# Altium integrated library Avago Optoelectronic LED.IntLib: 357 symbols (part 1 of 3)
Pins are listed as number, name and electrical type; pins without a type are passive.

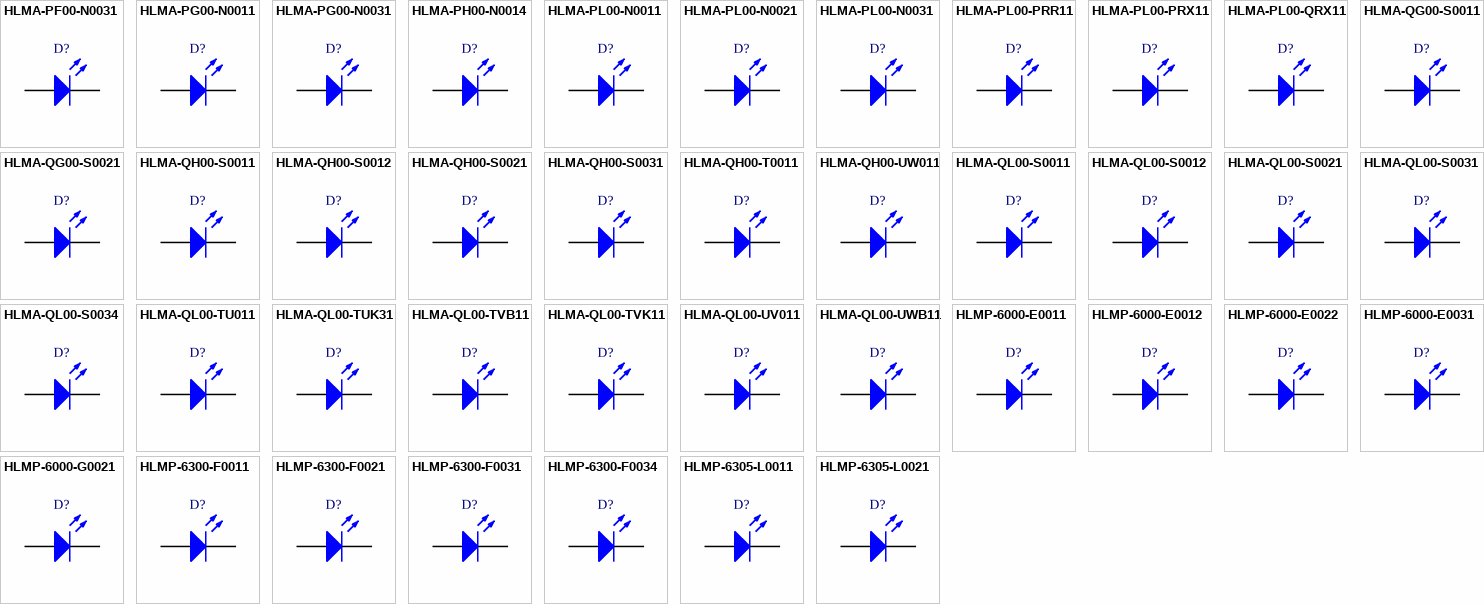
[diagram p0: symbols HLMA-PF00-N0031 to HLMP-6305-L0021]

## HLMA-PF00-N0031
designator D?
Subminiature High Performance AlInGaP Red LED Lamp; LuminousIntensity: 25mcd (Minimum).; PCB_Layout: Complies with manufacturer's recommendation.; DrillSize: Nominal, Rounded to nearest 0.05mm
footprint 2.2X2.1X2.2Z (SM LED; 2 Z-Bend Leads)
simulation model Agl_HLMPQG00 (Diode)
signal-integrity model LED
pins: 1 A, 2 K

## HLMA-PG00-N0011
designator D?
Subminiature High Performance AlInGaP Red LED Lamp; LuminousIntensity: 25mcd (Minimum).; PCB_Layout: Complies with manufacturer's recommendation.
footprint 2.2X2.1X2.2 (SM LED; 2 Gull Wing Leads; Body 2.2 x 2.1 mm, (LxW))
simulation model Agl_HLMPQG00 (Diode)
signal-integrity model LED
pins: 1 A, 2 K

## HLMA-PG00-N0031
designator D?
Subminiature High Performance AlInGaP Red LED Lamp; LuminousIntensity: 25mcd (Minimum).; PCB_Layout: Complies with manufacturer's recommendation.; DrillSize: Nominal, Rounded to nearest 0.05mm
footprint 2.2X2.1X2.2Z (SM LED; 2 Z-Bend Leads)
simulation model Agl_HLMPQG00 (Diode)
signal-integrity model LED
pins: 1 A, 2 K

## HLMA-PH00-N0014
designator D?
Subminiature High Performance AlInGaP Red/Orange LED Lamp; LuminousIntensity: 25mcd (Minimum).; LED_Colour: Red & Orange; PCB_Layout: Complies with manufacturer's recommendation.
footprint 2.2X2.1X2.2 (SM LED; 2 Gull Wing Leads; Body 2.2 x 2.1 mm, (LxW))
simulation model Agl_HLMPQG00 (Diode)
signal-integrity model LED
pins: 1 A, 2 K

## HLMA-PL00-N0011
designator D?
Subminiature High Performance AlInGaP Amber LED Lamp; LuminousIntensity: 25mcd (Minimum).; PCB_Layout: Complies with manufacturer's recommendation.
footprint 2.2X2.1X2.2 (SM LED; 2 Gull Wing Leads; Body 2.2 x 2.1 mm, (LxW))
simulation model Agl_HLMPQG00 (Diode)
signal-integrity model LED
pins: 1 A, 2 K

## HLMA-PL00-N0021
designator D?
Subminiature High Performance AlInGaP Amber LED Lamp; LuminousIntensity: 25mcd (Minimum).; PCB_Layout: Complies with manufacturer's recommendation.; DrillSize: Nominal, Rounded to nearest 0.05mm
footprint 2.2X2.1X2.2Y (SM LED; 2 Yoke Leads)
simulation model Agl_HLMPQG00 (Diode)
signal-integrity model LED
pins: 1 A, 2 K

## HLMA-PL00-N0031
designator D?
Subminiature High Performance AlInGaP Amber LED Lamp; LuminousIntensity: 25mcd (Minimum).; PCB_Layout: Complies with manufacturer's recommendation.; DrillSize: Nominal, Rounded to nearest 0.05mm
footprint 2.2X2.1X2.2Z (SM LED; 2 Z-Bend Leads)
simulation model Agl_HLMPQG00 (Diode)
signal-integrity model LED
pins: 1 A, 2 K

## HLMA-PL00-PRR11
designator D?
Subminiature High Performance AlInGaP Amber LED Lamp; LuminousIntensity: 40mcd (Minimum).; PCB_Layout: Complies with manufacturer's recommendation.
footprint 2.2X2.1X2.2 (SM LED; 2 Gull Wing Leads; Body 2.2 x 2.1 mm, (LxW))
simulation model Agl_HLMPQG00 (Diode)
signal-integrity model LED
pins: 1 A, 2 K

## HLMA-PL00-PRX11
designator D?
Subminiature High Performance AlInGaP Amber LED Lamp; LuminousIntensity: 40mcd (Minimum).; PCB_Layout: Complies with manufacturer's recommendation.
footprint 2.2X2.1X2.2 (SM LED; 2 Gull Wing Leads; Body 2.2 x 2.1 mm, (LxW))
simulation model Agl_HLMPQG00 (Diode)
signal-integrity model LED
pins: 1 A, 2 K

## HLMA-PL00-QRX11
designator D?
Subminiature High Performance AlInGaP Amber LED Lamp; LuminousIntensity: 63mcd (Minimum).; PCB_Layout: Complies with manufacturer's recommendation.
footprint 2.2X2.1X2.2 (SM LED; 2 Gull Wing Leads; Body 2.2 x 2.1 mm, (LxW))
simulation model Agl_HLMPQG00 (Diode)
signal-integrity model LED
pins: 1 A, 2 K

## HLMA-QG00-S0011
designator D?
Subminiature High Performance AS AlInGaP Red LED Lamp; LuminousIntensity: 160mcd (Minimum).; PCB_Layout: Complies with manufacturer's recommendation.; DrillSize: Nominal, Rounded to nearest 0.05mm
footprint 2.2X2.1X2.9 (SM LED; 2 Gull Wing Leads; Body 2.2 x 2.1 mm, (LxW))
simulation model Agl_HLMPQG00 (Diode)
signal-integrity model LED
pins: 1 A, 2 K

## HLMA-QG00-S0021
designator D?
Subminiature High Performance AS AlInGaP Red LED Lamp; LuminousIntensity: 160mcd (Minimum).; PCB_Layout: Complies with manufacturer's recommendation.; DrillSize: Nominal, Rounded to nearest 0.05mm
footprint 2.2X2.1X2.9Y (SM LED; 2 Yoke Leads)
simulation model Agl_HLMPQG00 (Diode)
signal-integrity model LED
pins: 1 A, 2 K

## HLMA-QH00-S0011
designator D?
Subminiature High Performance AS AlInGaP Red/Orange LED Lamp; LuminousIntensity: 160mcd (Minimum).; LED_Colour: Red & Orange; PCB_Layout: Complies with manufacturer's recommendation.
footprint 2.2X2.1X2.9 (SM LED; 2 Gull Wing Leads; Body 2.2 x 2.1 mm, (LxW))
simulation model Agl_HLMPQG00 (Diode)
signal-integrity model LED
pins: 1 A, 2 K

## HLMA-QH00-S0012
designator D?
Subminiature High Performance AS AlInGaP Red/Orange LED Lamp; LuminousIntensity: 160mcd (Minimum).; LED_Colour: Red & Orange; PCB_Layout: Complies with manufacturer's recommendation.
footprint 2.2X2.1X2.9 (SM LED; 2 Gull Wing Leads; Body 2.2 x 2.1 mm, (LxW))
simulation model Agl_HLMPQG00 (Diode)
signal-integrity model LED
pins: 1 A, 2 K

## HLMA-QH00-S0021
designator D?
Subminiature High Performance AlInGaP Red/Orange LED Lamp; LuminousIntensity: 160mcd (Minimum).; LED_Colour: Red & Orange; PCB_Layout: Complies with manufacturer's recommendation.; DrillSize: Nominal, Rounded to nearest 0.05mm
footprint 2.2X2.1X2.9Y (SM LED; 2 Yoke Leads)
simulation model Agl_HLMPQG00 (Diode)
signal-integrity model LED
pins: 1 A, 2 K

## HLMA-QH00-S0031
designator D?
Subminiature High Performance AlInGaP Red/Orange LED Lamp; LuminousIntensity: 160mcd (Minimum).; LED_Colour: Red & Orange; PCB_Layout: Complies with manufacturer's recommendation.; DrillSize: Nominal, Rounded to nearest 0.05mm
footprint 2.2X2.1X2.9Z (SM LED; 2 Z-Bend Leads)
simulation model Agl_HLMPQG00 (Diode)
signal-integrity model LED
pins: 1 A, 2 K

## HLMA-QH00-T0011
designator D?
Subminiature High Performance AlInGaP Red/Orange LED Lamp; LuminousIntensity: 250mcd (Minimum).; LED_Colour: Red & Orange; PCB_Layout: Complies with manufacturer's recommendation.
footprint 2.2X2.1X2.9 (SM LED; 2 Gull Wing Leads; Body 2.2 x 2.1 mm, (LxW))
simulation model Agl_HLMPQG00 (Diode)
signal-integrity model LED
pins: 1 A, 2 K

## HLMA-QH00-UW011
designator D?
Subminiature High Performance AlInGaP Red/Orange LED Lamp; LuminousIntensity: 400mcd (Minimum).; LED_Colour: Red & Orange; PCB_Layout: Complies with manufacturer's recommendation.
footprint 2.2X2.1X2.9 (SM LED; 2 Gull Wing Leads; Body 2.2 x 2.1 mm, (LxW))
simulation model Agl_HLMPQG00 (Diode)
signal-integrity model LED
pins: 1 A, 2 K

## HLMA-QL00-S0011
designator D?
Subminiature High Performance AlInGaP Amber LED Lamp; LuminousIntensity: 160mcd (Minimum).; PCB_Layout: Complies with manufacturer's recommendation.
footprint 2.2X2.1X2.9 (SM LED; 2 Gull Wing Leads; Body 2.2 x 2.1 mm, (LxW))
simulation model Agl_HLMPQG00 (Diode)
signal-integrity model LED
pins: 1 A, 2 K

## HLMA-QL00-S0012
designator D?
Subminiature High Performance AlInGaP Amber LED Lamp; LuminousIntensity: 160mcd (Minimum).; PCB_Layout: Complies with manufacturer's recommendation.
footprint 2.2X2.1X2.9 (SM LED; 2 Gull Wing Leads; Body 2.2 x 2.1 mm, (LxW))
simulation model Agl_HLMPQG00 (Diode)
signal-integrity model LED
pins: 1 A, 2 K

## HLMA-QL00-S0021
designator D?
Subminiature High Performance AlInGaP Amber LED Lamp; LuminousIntensity: 160mcd (Minimum).; PCB_Layout: Complies with manufacturer's recommendation.; DrillSize: Nominal, Rounded to nearest 0.05mm
footprint 2.2X2.1X2.9Y (SM LED; 2 Yoke Leads)
simulation model Agl_HLMPQG00 (Diode)
signal-integrity model LED
pins: 1 A, 2 K

## HLMA-QL00-S0031
designator D?
Subminiature High Performance AlInGaP Amber LED Lamp; LuminousIntensity: 160mcd (Minimum).; PCB_Layout: Complies with manufacturer's recommendation.; DrillSize: Nominal, Rounded to nearest 0.05mm
footprint 2.2X2.1X2.9Z (SM LED; 2 Z-Bend Leads)
simulation model Agl_HLMPQG00 (Diode)
signal-integrity model LED
pins: 1 A, 2 K

## HLMA-QL00-S0034
designator D?
Subminiature High Performance AlInGaP Amber LED Lamp; LuminousIntensity: 160mcd (Minimum).; PCB_Layout: Complies with manufacturer's recommendation.; DrillSize: Nominal, Rounded to nearest 0.05mm
footprint 2.2X2.1X2.9Z (SM LED; 2 Z-Bend Leads)
simulation model Agl_HLMPQG00 (Diode)
signal-integrity model LED
pins: 1 A, 2 K

## HLMA-QL00-TU011
designator D?
Subminiature High Performance AlInGaP Amber LED Lamp; LuminousIntensity: 250mcd (Minimum).; PCB_Layout: Complies with manufacturer's recommendation.
footprint 2.2X2.1X2.9 (SM LED; 2 Gull Wing Leads; Body 2.2 x 2.1 mm, (LxW))
simulation model Agl_HLMPQG00 (Diode)
signal-integrity model LED
pins: 1 A, 2 K

## HLMA-QL00-TUK31
designator D?
Subminiature High Performance AlInGaP Amber LED Lamp; LuminousIntensity: 250mcd (Minimum).; PCB_Layout: Complies with manufacturer's recommendation.; DrillSize: Nominal, Rounded to nearest 0.05mm
footprint 2.2X2.1X2.9Z (SM LED; 2 Z-Bend Leads)
simulation model Agl_HLMPQG00 (Diode)
signal-integrity model LED
pins: 1 A, 2 K

## HLMA-QL00-TVB11
designator D?
Subminiature High Performance AlInGaP Amber LED Lamp; LuminousIntensity: 250mcd (Minimum).; PCB_Layout: Complies with manufacturer's recommendation.
footprint 2.2X2.1X2.9 (SM LED; 2 Gull Wing Leads; Body 2.2 x 2.1 mm, (LxW))
simulation model Agl_HLMPQG00 (Diode)
signal-integrity model LED
pins: 1 A, 2 K

## HLMA-QL00-TVK11
designator D?
Subminiature High Performance AlInGaP Amber LED Lamp; LuminousIntensity: 250mcd (Minimum).; PCB_Layout: Complies with manufacturer's recommendation.
footprint 2.2X2.1X2.9 (SM LED; 2 Gull Wing Leads; Body 2.2 x 2.1 mm, (LxW))
simulation model Agl_HLMPQG00 (Diode)
signal-integrity model LED
pins: 1 A, 2 K

## HLMA-QL00-UV011
designator D?
Subminiature High Performance AlInGaP Amber LED Lamp; LuminousIntensity: 400mcd (Minimum).; PCB_Layout: Complies with manufacturer's recommendation.
footprint 2.2X2.1X2.9 (SM LED; 2 Gull Wing Leads; Body 2.2 x 2.1 mm, (LxW))
simulation model Agl_HLMPQG00 (Diode)
signal-integrity model LED
pins: 1 A, 2 K

## HLMA-QL00-UWB11
designator D?
Subminiature High Performance AlInGaP Amber LED Lamp; LuminousIntensity: 400mcd (Minimum).; PCB_Layout: Complies with manufacturer's recommendation.
footprint 2.2X2.1X2.9 (SM LED; 2 Gull Wing Leads; Body 2.2 x 2.1 mm, (LxW))
simulation model Agl_HLMPQG00 (Diode)
signal-integrity model LED
pins: 1 A, 2 K

## HLMP-6000-E0011
designator D?
Subminiature Red LED Lamp; LuminousIntensity: 0.63mcd (Minimum).; PCB_Layout: Complies with manufacturer's recommendation.
footprint 2.2X2.1X2.9 (SM LED; 2 Gull Wing Leads; Body 2.2 x 2.1 mm, (LxW))
simulation model HLMP6000 (SUBCKT)
signal-integrity model LED
pins: 1 A, 2 K

## HLMP-6000-E0012
designator D?
Subminiature Red LED Lamp; LuminousIntensity: 0.63mcd (Minimum).; PCB_Layout: Complies with manufacturer's recommendation.
footprint 2.2X2.1X2.9 (SM LED; 2 Gull Wing Leads; Body 2.2 x 2.1 mm, (LxW))
simulation model HLMP6000 (SUBCKT)
signal-integrity model LED
pins: 1 A, 2 K

## HLMP-6000-E0022
designator D?
Subminiature Red LED Lamp; LuminousIntensity: 0.63mcd (Minimum).; PCB_Layout: Complies with manufacturer's recommendation.; DrillSize: Nominal, Rounded to nearest 0.05mm
footprint 2.2X2.1X2.9Y (SM LED; 2 Yoke Leads)
simulation model HLMP6000 (SUBCKT)
signal-integrity model LED
pins: 1 A, 2 K

## HLMP-6000-E0031
designator D?
Subminiature Red LED Lamp; LuminousIntensity: 0.63mcd (Minimum).; PCB_Layout: Complies with manufacturer's recommendation.; DrillSize: Nominal, Rounded to nearest 0.05mm
footprint 2.2X2.1X2.9Z (SM LED; 2 Z-Bend Leads)
simulation model HLMP6000 (SUBCKT)
signal-integrity model LED
pins: 1 A, 2 K

## HLMP-6000-G0021
designator D?
Subminiature Red LED Lamp; LuminousIntensity: 1.6mcd (Minimum).; PCB_Layout: Complies with manufacturer's recommendation.; DrillSize: Nominal, Rounded to nearest 0.05mm
footprint 2.2X2.1X2.9Y (SM LED; 2 Yoke Leads)
simulation model HLMP6000 (SUBCKT)
signal-integrity model LED
pins: 1 A, 2 K

## HLMP-6300-F0011
designator D?
Subminiature Red LED Lamp; LuminousIntensity: 1mcd (Minimum).; PCB_Layout: Complies with manufacturer's recommendation.
footprint 2.2X2.1X2.9 (SM LED; 2 Gull Wing Leads; Body 2.2 x 2.1 mm, (LxW))
simulation model Agl_HLMP7000 (Diode)
signal-integrity model LED
pins: 1 A, 2 K

## HLMP-6300-F0021
designator D?
Subminiature Red LED Lamp; LuminousIntensity: 1mcd (Minimum).; PCB_Layout: Complies with manufacturer's recommendation.; DrillSize: Nominal, Rounded to nearest 0.05mm
footprint 2.2X2.1X2.9Y (SM LED; 2 Yoke Leads)
simulation model Agl_HLMP7000 (Diode)
signal-integrity model LED
pins: 1 A, 2 K

## HLMP-6300-F0031
designator D?
Subminiature Red LED Lamp; LuminousIntensity: 1mcd (Minimum).; PCB_Layout: Complies with manufacturer's recommendation.; DrillSize: Nominal, Rounded to nearest 0.05mm
footprint 2.2X2.1X2.9Z (SM LED; 2 Z-Bend Leads)
simulation model Agl_HLMP7000 (Diode)
signal-integrity model LED
pins: 1 A, 2 K

## HLMP-6300-F0034
designator D?
Subminiature Red LED Lamp; LuminousIntensity: 1mcd (Minimum).; PCB_Layout: Complies with manufacturer's recommendation.; DrillSize: Nominal, Rounded to nearest 0.05mm
footprint 2.2X2.1X2.9Z (SM LED; 2 Z-Bend Leads)
simulation model Agl_HLMP7000 (Diode)
signal-integrity model LED
pins: 1 A, 2 K

## HLMP-6305-L0011
designator D?
Subminiature Red LED Lamp; LuminousIntensity: 10mcd (Minimum).; PCB_Layout: Complies with manufacturer's recommendation.
footprint 2.2X2.1X2.9 (SM LED; 2 Gull Wing Leads; Body 2.2 x 2.1 mm, (LxW))
simulation model Agl_HLMP7000 (Diode)
signal-integrity model LED
pins: 1 A, 2 K

## HLMP-6305-L0021
designator D?
Subminiature Red LED Lamp; LuminousIntensity: 10mcd (Minimum).; PCB_Layout: Complies with manufacturer's recommendation.; DrillSize: Nominal, Rounded to nearest 0.05mm
footprint 2.2X2.1X2.9Y (SM LED; 2 Yoke Leads)
simulation model Agl_HLMP7000 (Diode)
signal-integrity model LED
pins: 1 A, 2 K

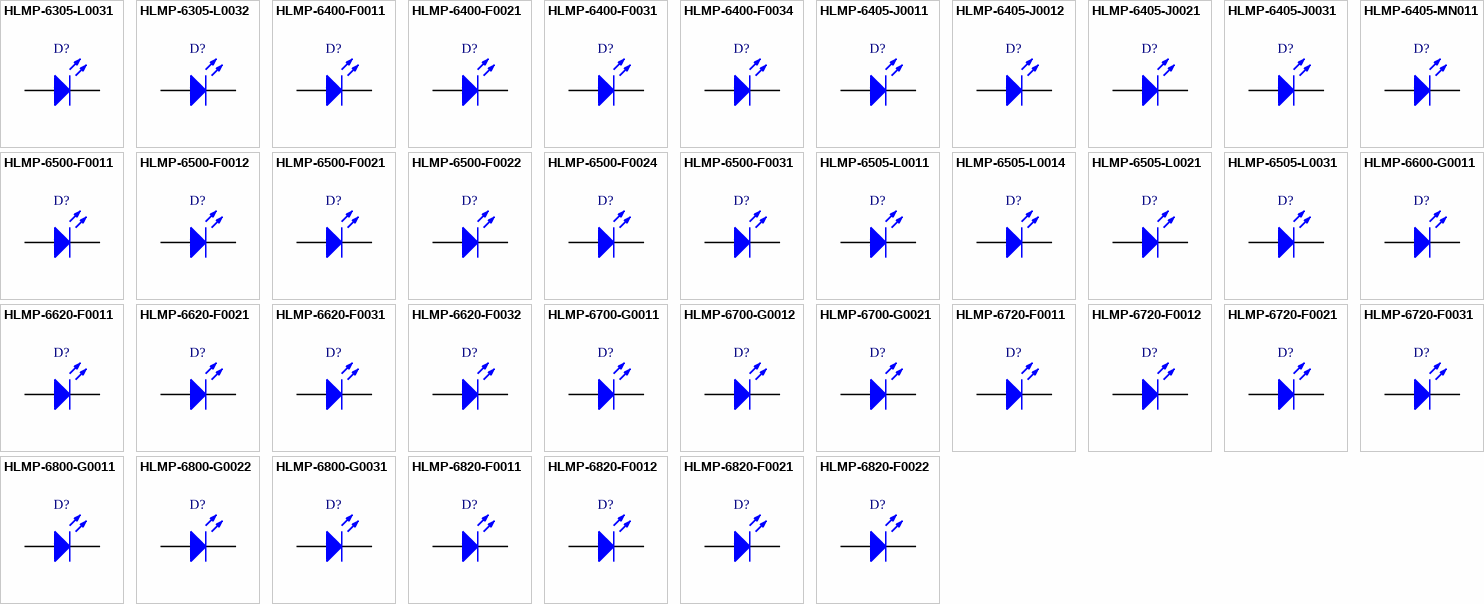
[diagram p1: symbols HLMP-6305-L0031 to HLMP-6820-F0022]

## HLMP-6305-L0031
designator D?
Subminiature Red LED Lamp; LuminousIntensity: 10mcd (Minimum).; PCB_Layout: Complies with manufacturer's recommendation.; DrillSize: Nominal, Rounded to nearest 0.05mm
footprint 2.2X2.1X2.9Z (SM LED; 2 Z-Bend Leads)
simulation model Agl_HLMP7000 (Diode)
signal-integrity model LED
pins: 1 A, 2 K

## HLMP-6305-L0032
designator D?
Subminiature Red LED Lamp; LuminousIntensity: 10mcd (Minimum).; PCB_Layout: Complies with manufacturer's recommendation.; DrillSize: Nominal, Rounded to nearest 0.05mm
footprint 2.2X2.1X2.9Z (SM LED; 2 Z-Bend Leads)
simulation model Agl_HLMP7000 (Diode)
signal-integrity model LED
pins: 1 A, 2 K

## HLMP-6400-F0011
designator D?
Subminiature Yellow LED Lamp; LuminousIntensity: 1mcd (Minimum).; PCB_Layout: Complies with manufacturer's recommendation.
footprint 2.2X2.1X2.9 (SM LED; 2 Gull Wing Leads; Body 2.2 x 2.1 mm, (LxW))
simulation model Agl_HLMP7019 (Diode)
signal-integrity model LED
pins: 1 A, 2 K

## HLMP-6400-F0021
designator D?
Subminiature Yellow LED Lamp; LuminousIntensity: 1mcd (Minimum).; PCB_Layout: Complies with manufacturer's recommendation.; DrillSize: Nominal, Rounded to nearest 0.05mm
footprint 2.2X2.1X2.9Y (SM LED; 2 Yoke Leads)
simulation model Agl_HLMP7019 (Diode)
signal-integrity model LED
pins: 1 A, 2 K

## HLMP-6400-F0031
designator D?
Subminiature Yellow LED Lamp; LuminousIntensity: 1mcd (Minimum).; PCB_Layout: Complies with manufacturer's recommendation.; DrillSize: Nominal, Rounded to nearest 0.05mm
footprint 2.2X2.1X2.9Z (SM LED; 2 Z-Bend Leads)
simulation model Agl_HLMP7019 (Diode)
signal-integrity model LED
pins: 1 A, 2 K

## HLMP-6400-F0034
designator D?
Subminiature Yellow LED Lamp; LuminousIntensity: 1mcd (Minimum).; PCB_Layout: Complies with manufacturer's recommendation.; DrillSize: Nominal, Rounded to nearest 0.05mm
footprint 2.2X2.1X2.9Z (SM LED; 2 Z-Bend Leads)
simulation model Agl_HLMP7019 (Diode)
signal-integrity model LED
pins: 1 A, 2 K

## HLMP-6405-J0011
designator D?
Subminiature Yellow LED Lamp; LuminousIntensity: 3.6mcd (Minimum).; PCB_Layout: Complies with manufacturer's recommendation.
footprint 2.2X2.1X2.9 (SM LED; 2 Gull Wing Leads; Body 2.2 x 2.1 mm, (LxW))
simulation model Agl_HLMP7019 (Diode)
signal-integrity model LED
pins: 1 A, 2 K

## HLMP-6405-J0012
designator D?
Subminiature Yellow LED Lamp; LuminousIntensity: 3.6mcd (Minimum).; PCB_Layout: Complies with manufacturer's recommendation.
footprint 2.2X2.1X2.9 (SM LED; 2 Gull Wing Leads; Body 2.2 x 2.1 mm, (LxW))
simulation model Agl_HLMP7019 (Diode)
signal-integrity model LED
pins: 1 A, 2 K

## HLMP-6405-J0021
designator D?
Subminiature Yellow LED Lamp; LuminousIntensity: 3.6mcd (Minimum).; PCB_Layout: Complies with manufacturer's recommendation.; DrillSize: Nominal, Rounded to nearest 0.05mm
footprint 2.2X2.1X2.9Y (SM LED; 2 Yoke Leads)
simulation model Agl_HLMP7019 (Diode)
signal-integrity model LED
pins: 1 A, 2 K

## HLMP-6405-J0031
designator D?
Subminiature Yellow LED Lamp; LuminousIntensity: 3.6mcd (Minimum).; PCB_Layout: Complies with manufacturer's recommendation.; DrillSize: Nominal, Rounded to nearest 0.05mm
footprint 2.2X2.1X2.9Z (SM LED; 2 Z-Bend Leads)
simulation model Agl_HLMP7019 (Diode)
signal-integrity model LED
pins: 1 A, 2 K

## HLMP-6405-MN011
designator D?
Subminiature Yellow LED Lamp; LuminousIntensity: 16mcd (Minimum).; PCB_Layout: Complies with manufacturer's recommendation.
footprint 2.2X2.1X2.9 (SM LED; 2 Gull Wing Leads; Body 2.2 x 2.1 mm, (LxW))
simulation model Agl_HLMP7019 (Diode)
signal-integrity model LED
pins: 1 A, 2 K

## HLMP-6500-F0011
designator D?
Subminiature Green LED Lamp; LuminousIntensity: 1mcd (Minimum).; PCB_Layout: Complies with manufacturer's recommendation.
footprint 2.2X2.1X2.9 (SM LED; 2 Gull Wing Leads; Body 2.2 x 2.1 mm, (LxW))
simulation model Agl_HLMP7040 (Diode)
signal-integrity model LED
pins: 1 A, 2 K

## HLMP-6500-F0012
designator D?
Subminiature Green LED Lamp; LuminousIntensity: 1mcd (Minimum).; PCB_Layout: Complies with manufacturer's recommendation.
footprint 2.2X2.1X2.9 (SM LED; 2 Gull Wing Leads; Body 2.2 x 2.1 mm, (LxW))
simulation model Agl_HLMP7040 (Diode)
signal-integrity model LED
pins: 1 A, 2 K

## HLMP-6500-F0021
designator D?
Subminiature Green LED Lamp; LuminousIntensity: 1mcd (Minimum).; PCB_Layout: Complies with manufacturer's recommendation.; DrillSize: Nominal, Rounded to nearest 0.05mm
footprint 2.2X2.1X2.9Y (SM LED; 2 Yoke Leads)
simulation model Agl_HLMP7040 (Diode)
signal-integrity model LED
pins: 1 A, 2 K

## HLMP-6500-F0022
designator D?
Subminiature Green LED Lamp; LuminousIntensity: 1mcd (Minimum).; PCB_Layout: Complies with manufacturer's recommendation.; DrillSize: Nominal, Rounded to nearest 0.05mm
footprint 2.2X2.1X2.9Y (SM LED; 2 Yoke Leads)
simulation model Agl_HLMP7040 (Diode)
signal-integrity model LED
pins: 1 A, 2 K

## HLMP-6500-F0024
designator D?
Subminiature Green LED Lamp; LuminousIntensity: 1mcd (Minimum).; PCB_Layout: Complies with manufacturer's recommendation.; DrillSize: Nominal, Rounded to nearest 0.05mm
footprint 2.2X2.1X2.9Y (SM LED; 2 Yoke Leads)
simulation model Agl_HLMP7040 (Diode)
signal-integrity model LED
pins: 1 A, 2 K

## HLMP-6500-F0031
designator D?
Subminiature Green LED Lamp; LuminousIntensity: 1mcd (Minimum).; PCB_Layout: Complies with manufacturer's recommendation.; DrillSize: Nominal, Rounded to nearest 0.05mm
footprint 2.2X2.1X2.9Z (SM LED; 2 Z-Bend Leads)
simulation model Agl_HLMP7040 (Diode)
signal-integrity model LED
pins: 1 A, 2 K

## HLMP-6505-L0011
designator D?
Subminiature Green LED Lamp; LuminousIntensity: 10mcd (Minimum).; PCB_Layout: Complies with manufacturer's recommendation.
footprint 2.2X2.1X2.9 (SM LED; 2 Gull Wing Leads; Body 2.2 x 2.1 mm, (LxW))
simulation model Agl_HLMP7040 (Diode)
signal-integrity model LED
pins: 1 A, 2 K

## HLMP-6505-L0014
designator D?
Subminiature Green LED Lamp; LuminousIntensity: 10mcd (Minimum).; PCB_Layout: Complies with manufacturer's recommendation.
footprint 2.2X2.1X2.9 (SM LED; 2 Gull Wing Leads; Body 2.2 x 2.1 mm, (LxW))
simulation model Agl_HLMP7040 (Diode)
signal-integrity model LED
pins: 1 A, 2 K

## HLMP-6505-L0021
designator D?
Subminiature Green LED Lamp; LuminousIntensity: 10mcd (Minimum).; PCB_Layout: Complies with manufacturer's recommendation.; DrillSize: Nominal, Rounded to nearest 0.05mm
footprint 2.2X2.1X2.9Y (SM LED; 2 Yoke Leads)
simulation model Agl_HLMP7040 (Diode)
signal-integrity model LED
pins: 1 A, 2 K

## HLMP-6505-L0031
designator D?
Subminiature Green LED Lamp; LuminousIntensity: 10mcd (Minimum).; PCB_Layout: Complies with manufacturer's recommendation.; DrillSize: Nominal, Rounded to nearest 0.05mm
footprint 2.2X2.1X2.9Z (SM LED; 2 Z-Bend Leads)
simulation model Agl_HLMP7040 (Diode)
signal-integrity model LED
pins: 1 A, 2 K

## HLMP-6600-G0011
designator D?
Subminiature Red LED Lamp; LuminousIntensity: 1.6mcd (Minimum).; PCB_Layout: Complies with manufacturer's recommendation.; Note: SIM model accounts for the Domed Subminiature Resistor. Extra resistance has been added to the parameter RS.
footprint 2.2X2.1X2.9 (SM LED; 2 Gull Wing Leads; Body 2.2 x 2.1 mm, (LxW))
simulation model Agl_HLMP6600 (Diode)
signal-integrity model LED
pins: 1 A, 2 K

## HLMP-6620-F0011
designator D?
Subminiature Red LED Lamp; LuminousIntensity: 1mcd (Minimum).; PCB_Layout: Complies with manufacturer's recommendation.; Note: SIM model accounts for the Domed Subminiature Resistor. Extra resistance has been added to the parameter RS.
footprint 2.2X2.1X2.9 (SM LED; 2 Gull Wing Leads; Body 2.2 x 2.1 mm, (LxW))
simulation model Agl_HLMP6620 (Diode)
signal-integrity model LED
pins: 1 A, 2 K

## HLMP-6620-F0021
designator D?
Subminiature Red LED Lamp; LuminousIntensity: 1mcd (Minimum).; PCB_Layout: Complies with manufacturer's recommendation.; DrillSize: Nominal, Rounded to nearest 0.05mm; Note: SIM model accounts for the Domed Subminiature Resistor. Extra resistance has been added to the parameter RS.
footprint 2.2X2.1X2.9Y (SM LED; 2 Yoke Leads)
simulation model Agl_HLMP6620 (Diode)
signal-integrity model LED
pins: 1 A, 2 K

## HLMP-6620-F0031
designator D?
Subminiature Red LED Lamp; LuminousIntensity: 1mcd (Minimum).; PCB_Layout: Complies with manufacturer's recommendation.; DrillSize: Nominal, Rounded to nearest 0.05mm; Note: SIM model accounts for the Domed Subminiature Resistor. Extra resistance has been added to the parameter RS.
footprint 2.2X2.1X2.9Z (SM LED; 2 Z-Bend Leads)
simulation model Agl_HLMP6620 (Diode)
signal-integrity model LED
pins: 1 A, 2 K

## HLMP-6620-F0032
designator D?
Subminiature Red LED Lamp; LuminousIntensity: 1mcd (Minimum).; PCB_Layout: Complies with manufacturer's recommendation.; DrillSize: Nominal, Rounded to nearest 0.05mm; Note: SIM model accounts for the Domed Subminiature Resistor. Extra resistance has been added to the parameter RS.
footprint 2.2X2.1X2.9Z (SM LED; 2 Z-Bend Leads)
simulation model Agl_HLMP6620 (Diode)
signal-integrity model LED
pins: 1 A, 2 K

## HLMP-6700-G0011
designator D?
Subminiature Yellow LED Lamp; LuminousIntensity: 1.4mcd (Minimum).; PCB_Layout: Complies with manufacturer's recommendation.; Note: SIM model accounts for the Domed Subminiature Resistor. Extra resistance has been added to the parameter RS.
footprint 2.2X2.1X2.9 (SM LED; 2 Gull Wing Leads; Body 2.2 x 2.1 mm, (LxW))
simulation model Agl_HLMP6700 (Diode)
signal-integrity model LED
pins: 1 A, 2 K

## HLMP-6700-G0012
designator D?
Subminiature Yellow LED Lamp; LuminousIntensity: 1.4mcd (Minimum).; PCB_Layout: Complies with manufacturer's recommendation.; Note: SIM model accounts for the Domed Subminiature Resistor. Extra resistance has been added to the parameter RS.
footprint 2.2X2.1X2.9 (SM LED; 2 Gull Wing Leads; Body 2.2 x 2.1 mm, (LxW))
simulation model Agl_HLMP6700 (Diode)
signal-integrity model LED
pins: 1 A, 2 K

## HLMP-6700-G0021
designator D?
Subminiature Yellow LED Lamp; LuminousIntensity: 1.4mcd (Minimum).; PCB_Layout: Complies with manufacturer's recommendation.; DrillSize: Nominal, Rounded to nearest 0.05mm; Note: SIM model accounts for the Domed Subminiature Resistor. Extra resistance has been added to the parameter RS.
footprint 2.2X2.1X2.9Y (SM LED; 2 Yoke Leads)
simulation model Agl_HLMP6700 (Diode)
signal-integrity model LED
pins: 1 A, 2 K

## HLMP-6720-F0011
designator D?
Subminiature Yellow LED Lamp; LuminousIntensity: 0.9mcd (Minimum).; PCB_Layout: Complies with manufacturer's recommendation.; Note: SIM model accounts for the Domed Subminiature Resistor. Extra resistance has been added to the parameter RS.
footprint 2.2X2.1X2.9 (SM LED; 2 Gull Wing Leads; Body 2.2 x 2.1 mm, (LxW))
simulation model Agl_HLMP6720 (Diode)
signal-integrity model LED
pins: 1 A, 2 K

## HLMP-6720-F0012
designator D?
Subminiature Yellow LED Lamp; LuminousIntensity: 0.9mcd (Minimum).; PCB_Layout: Complies with manufacturer's recommendation.; Note: SIM model accounts for the Domed Subminiature Resistor. Extra resistance has been added to the parameter RS.
footprint 2.2X2.1X2.9 (SM LED; 2 Gull Wing Leads; Body 2.2 x 2.1 mm, (LxW))
simulation model Agl_HLMP6720 (Diode)
signal-integrity model LED
pins: 1 A, 2 K

## HLMP-6720-F0021
designator D?
Subminiature Yellow LED Lamp; LuminousIntensity: 0.9mcd (Minimum).; PCB_Layout: Complies with manufacturer's recommendation.; DrillSize: Nominal, Rounded to nearest 0.05mm; Note: SIM model accounts for the Domed Subminiature Resistor. Extra resistance has been added to the parameter RS.
footprint 2.2X2.1X2.9Y (SM LED; 2 Yoke Leads)
simulation model Agl_HLMP6720 (Diode)
signal-integrity model LED
pins: 1 A, 2 K

## HLMP-6720-F0031
designator D?
Subminiature Yellow LED Lamp; LuminousIntensity: 0.9mcd (Minimum).; PCB_Layout: Complies with manufacturer's recommendation.; DrillSize: Nominal, Rounded to nearest 0.05mm; Note: SIM model accounts for the Domed Subminiature Resistor. Extra resistance has been added to the parameter RS.
footprint 2.2X2.1X2.9Z (SM LED; 2 Z-Bend Leads)
simulation model Agl_HLMP6720 (Diode)
signal-integrity model LED
pins: 1 A, 2 K

## HLMP-6800-G0011
designator D?
Subminiature Green LED Lamp; LuminousIntensity: 1.6mcd (Minimum).; PCB_Layout: Complies with manufacturer's recommendation.; Note: SIM model accounts for the Domed Subminiature Resistor. Extra resistance has been added to the parameter RS.
footprint 2.2X2.1X2.9 (SM LED; 2 Gull Wing Leads; Body 2.2 x 2.1 mm, (LxW))
simulation model Agl_HLMP6800 (Diode)
signal-integrity model LED
pins: 1 A, 2 K

## HLMP-6800-G0022
designator D?
Subminiature Green LED Lamp; LuminousIntensity: 1.6mcd (Minimum).; PCB_Layout: Complies with manufacturer's recommendation.; DrillSize: Nominal, Rounded to nearest 0.05mm; Note: SIM model accounts for the Domed Subminiature Resistor. Extra resistance has been added to the parameter RS.
footprint 2.2X2.1X2.9Y (SM LED; 2 Yoke Leads)
simulation model Agl_HLMP6800 (Diode)
signal-integrity model LED
pins: 1 A, 2 K

## HLMP-6800-G0031
designator D?
Subminiature Green LED Lamp; LuminousIntensity: 1.6mcd (Minimum).; PCB_Layout: Complies with manufacturer's recommendation.; DrillSize: Nominal, Rounded to nearest 0.05mm; Note: SIM model accounts for the Domed Subminiature Resistor. Extra resistance has been added to the parameter RS.
footprint 2.2X2.1X2.9Z (SM LED; 2 Z-Bend Leads)
simulation model Agl_HLMP6800 (Diode)
signal-integrity model LED
pins: 1 A, 2 K

## HLMP-6820-F0011
designator D?
Subminiature Green LED Lamp; LuminousIntensity: 1mcd (Minimum).; PCB_Layout: Complies with manufacturer's recommendation.; Note: SIM model accounts for the Domed Subminiature Resistor. Extra resistance has been added to the parameter RS.
footprint 2.2X2.1X2.9 (SM LED; 2 Gull Wing Leads; Body 2.2 x 2.1 mm, (LxW))
simulation model Agl_HLMP6820 (Diode)
signal-integrity model LED
pins: 1 A, 2 K

## HLMP-6820-F0012
designator D?
Subminiature Green LED Lamp; LuminousIntensity: 1mcd (Minimum).; PCB_Layout: Complies with manufacturer's recommendation.; Note: SIM model accounts for the Domed Subminiature Resistor. Extra resistance has been added to the parameter RS.
footprint 2.2X2.1X2.9 (SM LED; 2 Gull Wing Leads; Body 2.2 x 2.1 mm, (LxW))
simulation model Agl_HLMP6820 (Diode)
signal-integrity model LED
pins: 1 A, 2 K

## HLMP-6820-F0021
designator D?
Subminiature Green LED Lamp; LuminousIntensity: 1mcd (Minimum).; PCB_Layout: Complies with manufacturer's recommendation.; DrillSize: Nominal, Rounded to nearest 0.05mm; Note: SIM model accounts for the Domed Subminiature Resistor. Extra resistance has been added to the parameter RS.
footprint 2.2X2.1X2.9Y (SM LED; 2 Yoke Leads)
simulation model Agl_HLMP6820 (Diode)
signal-integrity model LED
pins: 1 A, 2 K

## HLMP-6820-F0022
designator D?
Subminiature Green LED Lamp; LuminousIntensity: 1mcd (Minimum).; PCB_Layout: Complies with manufacturer's recommendation.; DrillSize: Nominal, Rounded to nearest 0.05mm; Note: SIM model accounts for the Domed Subminiature Resistor. Extra resistance has been added to the parameter RS.
footprint 2.2X2.1X2.9Y (SM LED; 2 Yoke Leads)
simulation model Agl_HLMP6820 (Diode)
signal-integrity model LED
pins: 1 A, 2 K

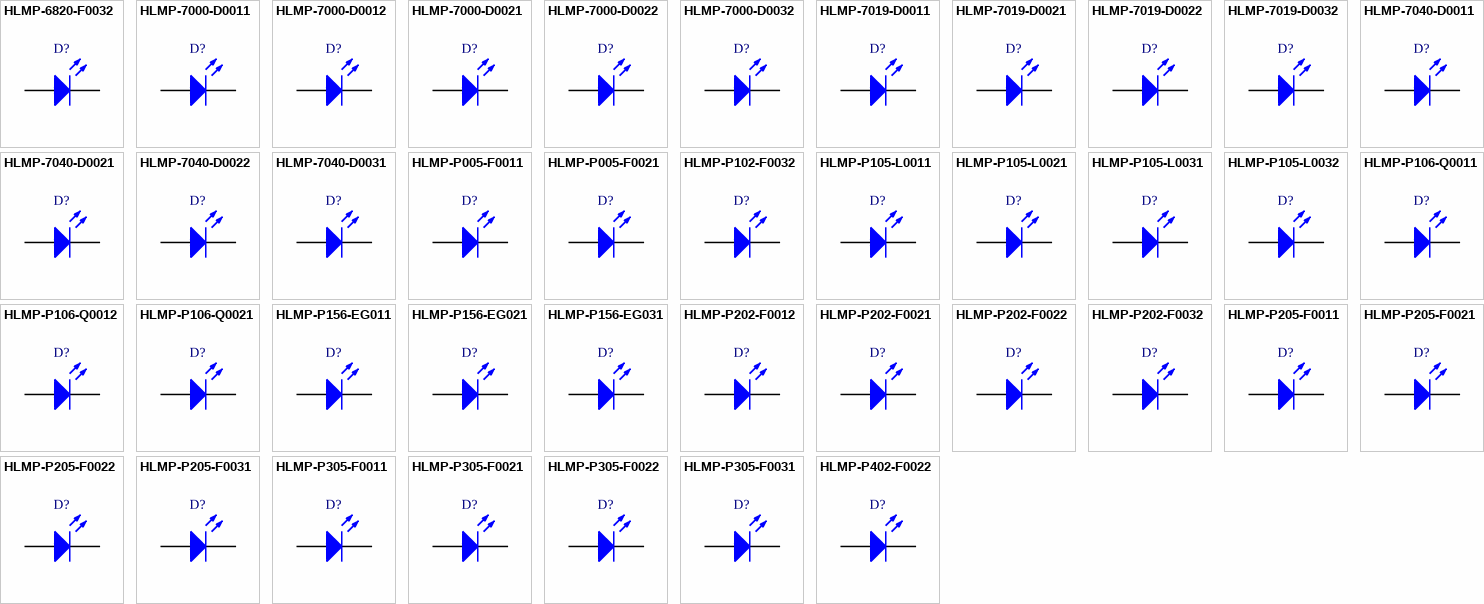
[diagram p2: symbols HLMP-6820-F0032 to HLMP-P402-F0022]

## HLMP-6820-F0032
designator D?
Subminiature Green LED Lamp; LuminousIntensity: 1mcd (Minimum).; PCB_Layout: Complies with manufacturer's recommendation.; DrillSize: Nominal, Rounded to nearest 0.05mm; Note: SIM model accounts for the Domed Subminiature Resistor. Extra resistance has been added to the parameter RS.
footprint 2.2X2.1X2.9Z (SM LED; 2 Z-Bend Leads)
simulation model Agl_HLMP6820 (Diode)
signal-integrity model LED
pins: 1 A, 2 K

## HLMP-7000-D0011
designator D?
Subminiature Red LED Lamp; LuminousIntensity: 0.4mcd (Minimum).; PCB_Layout: Complies with manufacturer's recommendation.
footprint 2.2X2.1X2.9 (SM LED; 2 Gull Wing Leads; Body 2.2 x 2.1 mm, (LxW))
simulation model Agl_HLMP7000 (Diode)
signal-integrity model LED
pins: 1 A, 2 K

## HLMP-7000-D0012
designator D?
Subminiature Red LED Lamp; LuminousIntensity: 0.4mcd (Minimum).; PCB_Layout: Complies with manufacturer's recommendation.
footprint 2.2X2.1X2.9 (SM LED; 2 Gull Wing Leads; Body 2.2 x 2.1 mm, (LxW))
simulation model Agl_HLMP7000 (Diode)
signal-integrity model LED
pins: 1 A, 2 K

## HLMP-7000-D0021
designator D?
Subminiature Red LED Lamp; LuminousIntensity: 0.4mcd (Minimum).; PCB_Layout: Complies with manufacturer's recommendation.; DrillSize: Nominal, Rounded to nearest 0.05mm
footprint 2.2X2.1X2.9Y (SM LED; 2 Yoke Leads)
simulation model Agl_HLMP7000 (Diode)
signal-integrity model LED
pins: 1 A, 2 K

## HLMP-7000-D0022
designator D?
Subminiature Red LED Lamp; LuminousIntensity: 0.4mcd (Minimum).; PCB_Layout: Complies with manufacturer's recommendation.; DrillSize: Nominal, Rounded to nearest 0.05mm
footprint 2.2X2.1X2.9Y (SM LED; 2 Yoke Leads)
simulation model Agl_HLMP7000 (Diode)
signal-integrity model LED
pins: 1 A, 2 K

## HLMP-7000-D0032
designator D?
Subminiature Red LED Lamp; LuminousIntensity: 0.4mcd (Minimum).; PCB_Layout: Complies with manufacturer's recommendation.; DrillSize: Nominal, Rounded to nearest 0.05mm
footprint 2.2X2.1X2.9Z (SM LED; 2 Z-Bend Leads)
simulation model Agl_HLMP7000 (Diode)
signal-integrity model LED
pins: 1 A, 2 K

## HLMP-7019-D0011
designator D?
Subminiature Yellow LED Lamp; LuminousIntensity: 0.4mcd (Minimum).; PCB_Layout: Complies with manufacturer's recommendation.
footprint 2.2X2.1X2.9 (SM LED; 2 Gull Wing Leads; Body 2.2 x 2.1 mm, (LxW))
simulation model Agl_HLMP7019 (Diode)
signal-integrity model LED
pins: 1 A, 2 K

## HLMP-7019-D0021
designator D?
Subminiature Yellow LED Lamp; LuminousIntensity: 0.4mcd (Minimum).; PCB_Layout: Complies with manufacturer's recommendation.; DrillSize: Nominal, Rounded to nearest 0.05mm
footprint 2.2X2.1X2.9Y (SM LED; 2 Yoke Leads)
simulation model Agl_HLMP7019 (Diode)
signal-integrity model LED
pins: 1 A, 2 K

## HLMP-7019-D0022
designator D?
Subminiature Yellow LED Lamp; LuminousIntensity: 0.4mcd (Minimum).; PCB_Layout: Complies with manufacturer's recommendation.; DrillSize: Nominal, Rounded to nearest 0.05mm
footprint 2.2X2.1X2.9Y (SM LED; 2 Yoke Leads)
simulation model Agl_HLMP7019 (Diode)
signal-integrity model LED
pins: 1 A, 2 K

## HLMP-7019-D0032
designator D?
Subminiature Yellow LED Lamp; LuminousIntensity: 0.4mcd (Minimum).; PCB_Layout: Complies with manufacturer's recommendation.; DrillSize: Nominal, Rounded to nearest 0.05mm
footprint 2.2X2.1X2.9Z (SM LED; 2 Z-Bend Leads)
simulation model Agl_HLMP7019 (Diode)
signal-integrity model LED
pins: 1 A, 2 K

## HLMP-7040-D0011
designator D?
Subminiature Green LED Lamp; LuminousIntensity: 0.4mcd (Minimum).; PCB_Layout: Complies with manufacturer's recommendation.
footprint 2.2X2.1X2.9 (SM LED; 2 Gull Wing Leads; Body 2.2 x 2.1 mm, (LxW))
simulation model Agl_HLMP7040 (Diode)
signal-integrity model LED
pins: 1 A, 2 K

## HLMP-7040-D0021
designator D?
Subminiature Green LED Lamp; LuminousIntensity: 0.4mcd (Minimum).; PCB_Layout: Complies with manufacturer's recommendation.; DrillSize: Nominal, Rounded to nearest 0.05mm
footprint 2.2X2.1X2.9Y (SM LED; 2 Yoke Leads)
simulation model Agl_HLMP7040 (Diode)
signal-integrity model LED
pins: 1 A, 2 K

## HLMP-7040-D0022
designator D?
Subminiature Green LED Lamp; LuminousIntensity: 0.4mcd (Minimum).; PCB_Layout: Complies with manufacturer's recommendation.; DrillSize: Nominal, Rounded to nearest 0.05mm
footprint 2.2X2.1X2.9Y (SM LED; 2 Yoke Leads)
simulation model Agl_HLMP7040 (Diode)
signal-integrity model LED
pins: 1 A, 2 K

## HLMP-7040-D0031
designator D?
Subminiature Green LED Lamp; LuminousIntensity: 0.4mcd (Minimum).; PCB_Layout: Complies with manufacturer's recommendation.; DrillSize: Nominal, Rounded to nearest 0.05mm
footprint 2.2X2.1X2.9Z (SM LED; 2 Z-Bend Leads)
simulation model Agl_HLMP7040 (Diode)
signal-integrity model LED
pins: 1 A, 2 K

## HLMP-P005-F0011
designator D?
Subminiature Red LED Lamp; LuminousIntensity: 1mcd (Minimum).; PCB_Layout: Complies with manufacturer's recommendation.
footprint 2.2X2.1X2.2 (SM LED; 2 Gull Wing Leads; Body 2.2 x 2.1 mm, (LxW))
simulation model Agl_HLMP6000 (Diode)
signal-integrity model LED
pins: 1 A, 2 K

## HLMP-P005-F0021
designator D?
Subminiature Red LED Lamp; LuminousIntensity: 1mcd (Minimum).; PCB_Layout: Complies with manufacturer's recommendation.; DrillSize: Nominal, Rounded to nearest 0.05mm
footprint 2.2X2.1X2.2Y (SM LED; 2 Yoke Leads)
simulation model Agl_HLMP6000 (Diode)
signal-integrity model LED
pins: 1 A, 2 K

## HLMP-P102-F0032
designator D?
Subminiature High Performance TS AlGaAs Red LED Lamp; LuminousIntensity: 1mcd (Minimum).; PCB_Layout: Complies with manufacturer's recommendation.; DrillSize: Nominal, Rounded to nearest 0.05mm
footprint 2.2X2.1X2.2Z (SM LED; 2 Z-Bend Leads)
simulation model Agl_HLMPQ100 (Diode)
signal-integrity model LED
pins: 1 A, 2 K

## HLMP-P105-L0011
designator D?
Subminiature Red LED Lamp; LuminousIntensity: 10mcd (Minimum).; PCB_Layout: Complies with manufacturer's recommendation.
footprint 2.2X2.1X2.2 (SM LED; 2 Gull Wing Leads; Body 2.2 x 2.1 mm, (LxW))
simulation model Agl_HLMPQ100 (Diode)
signal-integrity model LED
pins: 1 A, 2 K

## HLMP-P105-L0021
designator D?
Subminiature Red LED Lamp; LuminousIntensity: 10mcd (Minimum).; PCB_Layout: Complies with manufacturer's recommendation.; DrillSize: Nominal, Rounded to nearest 0.05mm
footprint 2.2X2.1X2.2Y (SM LED; 2 Yoke Leads)
simulation model Agl_HLMPQ100 (Diode)
signal-integrity model LED
pins: 1 A, 2 K

## HLMP-P105-L0031
designator D?
Subminiature Red LED Lamp; LuminousIntensity: 10mcd (Minimum).; PCB_Layout: Complies with manufacturer's recommendation.; DrillSize: Nominal, Rounded to nearest 0.05mm
footprint 2.2X2.1X2.2Z (SM LED; 2 Z-Bend Leads)
simulation model Agl_HLMPQ100 (Diode)
signal-integrity model LED
pins: 1 A, 2 K

## HLMP-P105-L0032
designator D?
Subminiature Red LED Lamp; LuminousIntensity: 10mcd (Minimum).; PCB_Layout: Complies with manufacturer's recommendation.; DrillSize: Nominal, Rounded to nearest 0.05mm
footprint 2.2X2.1X2.2Z (SM LED; 2 Z-Bend Leads)
simulation model Agl_HLMPQ100 (Diode)
signal-integrity model LED
pins: 1 A, 2 K

## HLMP-P106-Q0011
designator D?
Subminiature High Performance TS AlGaAs Red LED Lamp; LuminousIntensity: 63mcd (Minimum).; PCB_Layout: Complies with manufacturer's recommendation.
footprint 2.2X2.1X2.2 (SM LED; 2 Gull Wing Leads; Body 2.2 x 2.1 mm, (LxW))
simulation model Agl_HLMPQ102 (Diode)
signal-integrity model LED
pins: 1 A, 2 K

## HLMP-P106-Q0012
designator D?
Subminiature High Performance TS AlGaAs Red LED Lamp; LuminousIntensity: 63mcd (Minimum).; PCB_Layout: Complies with manufacturer's recommendation.
footprint 2.2X2.1X2.2 (SM LED; 2 Gull Wing Leads; Body 2.2 x 2.1 mm, (LxW))
simulation model Agl_HLMPQ102 (Diode)
signal-integrity model LED
pins: 1 A, 2 K

## HLMP-P106-Q0021
designator D?
Subminiature High Performance TS AlGaAs Red LED Lamp; LuminousIntensity: 63mcd (Minimum).; PCB_Layout: Complies with manufacturer's recommendation.; DrillSize: Nominal, Rounded to nearest 0.05mm
footprint 2.2X2.1X2.2Y (SM LED; 2 Yoke Leads)
simulation model Agl_HLMPQ102 (Diode)
signal-integrity model LED
pins: 1 A, 2 K

## HLMP-P156-EG011
designator D?
Subminiature High Performance TS AlGaAs Red LED Lamp; LuminousIntensity: 0.63mcd (Minimum).; PCB_Layout: Complies with manufacturer's recommendation.
footprint 2.2X2.1X2.2 (SM LED; 2 Gull Wing Leads; Body 2.2 x 2.1 mm, (LxW))
simulation model Agl_HLMPQ152 (Diode)
signal-integrity model LED
pins: 1 A, 2 K

## HLMP-P156-EG021
designator D?
Subminiature High Performance TS AlGaAs Red LED Lamp; LuminousIntensity: 0.63mcd (Minimum).; PCB_Layout: Complies with manufacturer's recommendation.; DrillSize: Nominal, Rounded to nearest 0.05mm
footprint 2.2X2.1X2.2Y (SM LED; 2 Yoke Leads)
simulation model Agl_HLMPQ152 (Diode)
signal-integrity model LED
pins: 1 A, 2 K

## HLMP-P156-EG031
designator D?
Subminiature High Performance TS AlGaAs Red LED Lamp; LuminousIntensity: 0.63mcd (Minimum).; PCB_Layout: Complies with manufacturer's recommendation.; DrillSize: Nominal, Rounded to nearest 0.05mm
footprint 2.2X2.1X2.2Z (SM LED; 2 Z-Bend Leads)
simulation model Agl_HLMPQ152 (Diode)
signal-integrity model LED
pins: 1 A, 2 K

## HLMP-P202-F0012
designator D?
Subminiature Red LED Lamp; LuminousIntensity: 1mcd (Minimum).; PCB_Layout: Complies with manufacturer's recommendation.
footprint 2.2X2.1X2.2 (SM LED; 2 Gull Wing Leads; Body 2.2 x 2.1 mm, (LxW))
simulation model Agl_HLMP7000 (Diode)
signal-integrity model LED
pins: 1 A, 2 K

## HLMP-P202-F0021
designator D?
Subminiature Red LED Lamp; LuminousIntensity: 1mcd (Minimum).; PCB_Layout: Complies with manufacturer's recommendation.; DrillSize: Nominal, Rounded to nearest 0.05mm
footprint 2.2X2.1X2.2Y (SM LED; 2 Yoke Leads)
simulation model Agl_HLMP7000 (Diode)
signal-integrity model LED
pins: 1 A, 2 K

## HLMP-P202-F0022
designator D?
Subminiature Red LED Lamp; LuminousIntensity: 1mcd (Minimum).; PCB_Layout: Complies with manufacturer's recommendation.; DrillSize: Nominal, Rounded to nearest 0.05mm
footprint 2.2X2.1X2.2Y (SM LED; 2 Yoke Leads)
simulation model Agl_HLMP7000 (Diode)
signal-integrity model LED
pins: 1 A, 2 K

## HLMP-P202-F0032
designator D?
Subminiature Red LED Lamp; LuminousIntensity: 1mcd (Minimum).; PCB_Layout: Complies with manufacturer's recommendation.; DrillSize: Nominal, Rounded to nearest 0.05mm
footprint 2.2X2.1X2.2Z (SM LED; 2 Z-Bend Leads)
simulation model Agl_HLMP7000 (Diode)
signal-integrity model LED
pins: 1 A, 2 K

## HLMP-P205-F0011
designator D?
Subminiature Red LED Lamp; LuminousIntensity: 1mcd (Minimum).; PCB_Layout: Complies with manufacturer's recommendation.
footprint 2.2X2.1X2.2 (SM LED; 2 Gull Wing Leads; Body 2.2 x 2.1 mm, (LxW))
simulation model Agl_HLMP7000 (Diode)
signal-integrity model LED
pins: 1 A, 2 K

## HLMP-P205-F0021
designator D?
Subminiature Red LED Lamp; LuminousIntensity: 1mcd (Minimum).; PCB_Layout: Complies with manufacturer's recommendation.; DrillSize: Nominal, Rounded to nearest 0.05mm
footprint 2.2X2.1X2.2Y (SM LED; 2 Yoke Leads)
simulation model Agl_HLMP7000 (Diode)
signal-integrity model LED
pins: 1 A, 2 K

## HLMP-P205-F0022
designator D?
Subminiature Red LED Lamp; LuminousIntensity: 1mcd (Minimum).; PCB_Layout: Complies with manufacturer's recommendation.; DrillSize: Nominal, Rounded to nearest 0.05mm
footprint 2.2X2.1X2.2Y (SM LED; 2 Yoke Leads)
simulation model Agl_HLMP7000 (Diode)
signal-integrity model LED
pins: 1 A, 2 K

## HLMP-P205-F0031
designator D?
Subminiature Red LED Lamp; LuminousIntensity: 1mcd (Minimum).; PCB_Layout: Complies with manufacturer's recommendation.; DrillSize: Nominal, Rounded to nearest 0.05mm
footprint 2.2X2.1X2.2Z (SM LED; 2 Z-Bend Leads)
simulation model Agl_HLMP7000 (Diode)
signal-integrity model LED
pins: 1 A, 2 K

## HLMP-P305-F0011
designator D?
Subminiature Yellow LED Lamp; LuminousIntensity: 1mcd (Minimum).; PCB_Layout: Complies with manufacturer's recommendation.
footprint 2.2X2.1X2.2 (SM LED; 2 Gull Wing Leads; Body 2.2 x 2.1 mm, (LxW))
simulation model Agl_HLMP7019 (Diode)
signal-integrity model LED
pins: 1 A, 2 K

## HLMP-P305-F0021
designator D?
Subminiature Yellow LED Lamp; LuminousIntensity: 1mcd (Minimum).; PCB_Layout: Complies with manufacturer's recommendation.; DrillSize: Nominal, Rounded to nearest 0.05mm
footprint 2.2X2.1X2.2Y (SM LED; 2 Yoke Leads)
simulation model Agl_HLMP7019 (Diode)
signal-integrity model LED
pins: 1 A, 2 K

## HLMP-P305-F0022
designator D?
Subminiature Yellow LED Lamp; LuminousIntensity: 1mcd (Minimum).; PCB_Layout: Complies with manufacturer's recommendation.; DrillSize: Nominal, Rounded to nearest 0.05mm
footprint 2.2X2.1X2.2Y (SM LED; 2 Yoke Leads)
simulation model Agl_HLMP7019 (Diode)
signal-integrity model LED
pins: 1 A, 2 K

## HLMP-P305-F0031
designator D?
Subminiature Yellow LED Lamp; LuminousIntensity: 1mcd (Minimum).; PCB_Layout: Complies with manufacturer's recommendation.; DrillSize: Nominal, Rounded to nearest 0.05mm
footprint 2.2X2.1X2.2Z (SM LED; 2 Z-Bend Leads)
simulation model Agl_HLMP7019 (Diode)
signal-integrity model LED
pins: 1 A, 2 K

## HLMP-P402-F0022
designator D?
Subminiature Orange LED Lamp; LuminousIntensity: 1mcd (Minimum).; PCB_Layout: Complies with manufacturer's recommendation.; DrillSize: Nominal, Rounded to nearest 0.05mm
footprint 2.2X2.1X2.2Y (SM LED; 2 Yoke Leads)
simulation model Agl_HLMPQ400 (Diode)
signal-integrity model LED
pins: 1 A, 2 K

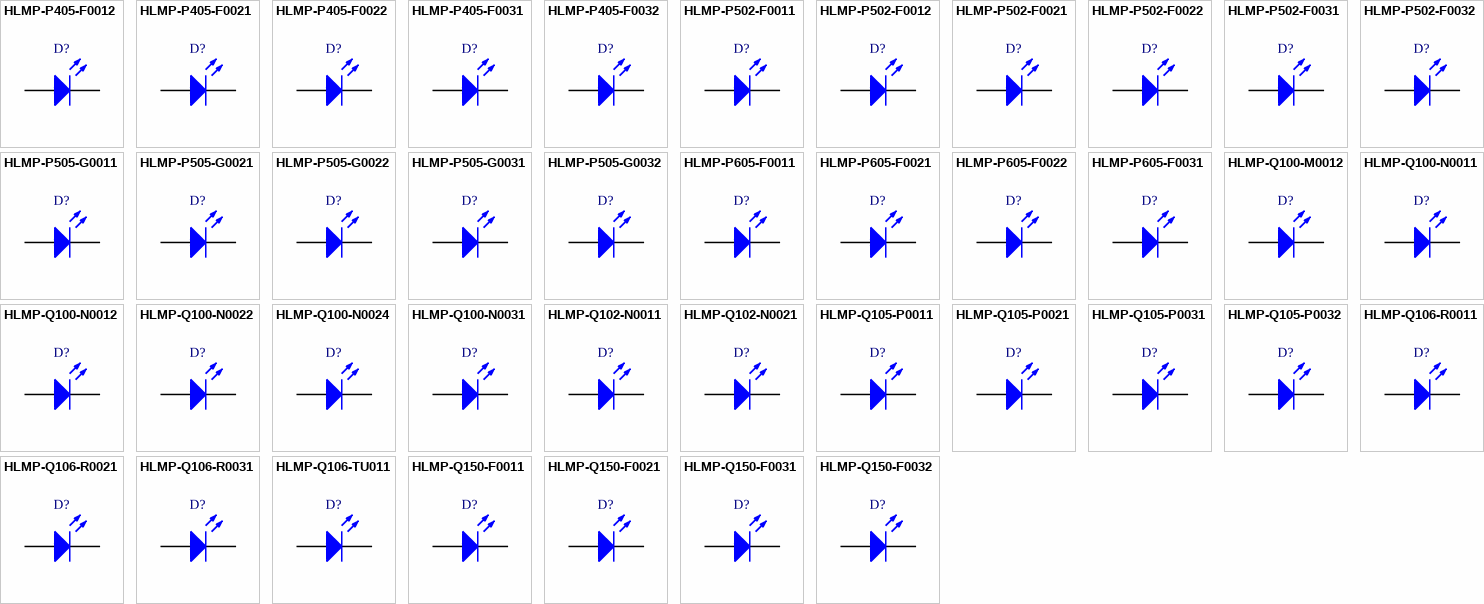
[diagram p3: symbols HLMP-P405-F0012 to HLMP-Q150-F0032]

## HLMP-P405-F0012
designator D?
Subminiature Orange LED Lamp; LuminousIntensity: 1mcd (Minimum).; PCB_Layout: Complies with manufacturer's recommendation.
footprint 2.2X2.1X2.2 (SM LED; 2 Gull Wing Leads; Body 2.2 x 2.1 mm, (LxW))
simulation model Agl_HLMPQ400 (Diode)
signal-integrity model LED
pins: 1 A, 2 K

## HLMP-P405-F0021
designator D?
Subminiature Orange LED Lamp; LuminousIntensity: 1mcd (Minimum).; PCB_Layout: Complies with manufacturer's recommendation.; DrillSize: Nominal, Rounded to nearest 0.05mm
footprint 2.2X2.1X2.2Y (SM LED; 2 Yoke Leads)
simulation model Agl_HLMPQ400 (Diode)
signal-integrity model LED
pins: 1 A, 2 K

## HLMP-P405-F0022
designator D?
Subminiature Orange LED Lamp; LuminousIntensity: 1mcd (Minimum).; PCB_Layout: Complies with manufacturer's recommendation.; DrillSize: Nominal, Rounded to nearest 0.05mm
footprint 2.2X2.1X2.2Y (SM LED; 2 Yoke Leads)
simulation model Agl_HLMPQ400 (Diode)
signal-integrity model LED
pins: 1 A, 2 K

## HLMP-P405-F0031
designator D?
Subminiature Orange LED Lamp; LuminousIntensity: 1mcd (Minimum).; PCB_Layout: Complies with manufacturer's recommendation.; DrillSize: Nominal, Rounded to nearest 0.05mm
footprint 2.2X2.1X2.2Z (SM LED; 2 Z-Bend Leads)
simulation model Agl_HLMPQ400 (Diode)
signal-integrity model LED
pins: 1 A, 2 K

## HLMP-P405-F0032
designator D?
Subminiature Orange LED Lamp; LuminousIntensity: 1mcd (Minimum).; PCB_Layout: Complies with manufacturer's recommendation.; DrillSize: Nominal, Rounded to nearest 0.05mm
footprint 2.2X2.1X2.2Z (SM LED; 2 Z-Bend Leads)
simulation model Agl_HLMPQ400 (Diode)
signal-integrity model LED
pins: 1 A, 2 K

## HLMP-P502-F0011
designator D?
Subminiature Green LED Lamp; LuminousIntensity: 1mcd (Minimum).; PCB_Layout: Complies with manufacturer's recommendation.
footprint 2.2X2.1X2.2 (SM LED; 2 Gull Wing Leads; Body 2.2 x 2.1 mm, (LxW))
simulation model Agl_HLMP7040 (Diode)
signal-integrity model LED
pins: 1 A, 2 K

## HLMP-P502-F0012
designator D?
Subminiature Green LED Lamp; LuminousIntensity: 1mcd (Minimum).; PCB_Layout: Complies with manufacturer's recommendation.
footprint 2.2X2.1X2.2 (SM LED; 2 Gull Wing Leads; Body 2.2 x 2.1 mm, (LxW))
simulation model Agl_HLMP7040 (Diode)
signal-integrity model LED
pins: 1 A, 2 K

## HLMP-P502-F0021
designator D?
Subminiature Green LED Lamp; LuminousIntensity: 1mcd (Minimum).; PCB_Layout: Complies with manufacturer's recommendation.; DrillSize: Nominal, Rounded to nearest 0.05mm
footprint 2.2X2.1X2.2Y (SM LED; 2 Yoke Leads)
simulation model Agl_HLMP7040 (Diode)
signal-integrity model LED
pins: 1 A, 2 K

## HLMP-P502-F0022
designator D?
Subminiature Green LED Lamp; LuminousIntensity: 1mcd (Minimum).; PCB_Layout: Complies with manufacturer's recommendation.; DrillSize: Nominal, Rounded to nearest 0.05mm
footprint 2.2X2.1X2.2Y (SM LED; 2 Yoke Leads)
simulation model Agl_HLMP7040 (Diode)
signal-integrity model LED
pins: 1 A, 2 K

## HLMP-P502-F0031
designator D?
Subminiature Green LED Lamp; LuminousIntensity: 1mcd (Minimum).; PCB_Layout: Complies with manufacturer's recommendation.; DrillSize: Nominal, Rounded to nearest 0.05mm
footprint 2.2X2.1X2.2Z (SM LED; 2 Z-Bend Leads)
simulation model Agl_HLMP7040 (Diode)
signal-integrity model LED
pins: 1 A, 2 K

## HLMP-P502-F0032
designator D?
Subminiature Green LED Lamp; LuminousIntensity: 1mcd (Minimum).; PCB_Layout: Complies with manufacturer's recommendation.; DrillSize: Nominal, Rounded to nearest 0.05mm
footprint 2.2X2.1X2.2Z (SM LED; 2 Z-Bend Leads)
simulation model Agl_HLMP7040 (Diode)
signal-integrity model LED
pins: 1 A, 2 K

## HLMP-P505-G0011
designator D?
Subminiature Green LED Lamp; LuminousIntensity: 1.6mcd (Minimum).; PCB_Layout: Complies with manufacturer's recommendation.
footprint 2.2X2.1X2.2 (SM LED; 2 Gull Wing Leads; Body 2.2 x 2.1 mm, (LxW))
simulation model Agl_HLMP7040 (Diode)
signal-integrity model LED
pins: 1 A, 2 K

## HLMP-P505-G0021
designator D?
Subminiature Green LED Lamp; LuminousIntensity: 1.6mcd (Minimum).; PCB_Layout: Complies with manufacturer's recommendation.; DrillSize: Nominal, Rounded to nearest 0.05mm
footprint 2.2X2.1X2.2Y (SM LED; 2 Yoke Leads)
simulation model Agl_HLMP7040 (Diode)
signal-integrity model LED
pins: 1 A, 2 K

## HLMP-P505-G0022
designator D?
Subminiature Green LED Lamp; LuminousIntensity: 1.6mcd (Minimum).; PCB_Layout: Complies with manufacturer's recommendation.; DrillSize: Nominal, Rounded to nearest 0.05mm
footprint 2.2X2.1X2.2Y (SM LED; 2 Yoke Leads)
simulation model Agl_HLMP7040 (Diode)
signal-integrity model LED
pins: 1 A, 2 K

## HLMP-P505-G0031
designator D?
Subminiature Green LED Lamp; LuminousIntensity: 1.6mcd (Minimum).; PCB_Layout: Complies with manufacturer's recommendation.; DrillSize: Nominal, Rounded to nearest 0.05mm
footprint 2.2X2.1X2.2Z (SM LED; 2 Z-Bend Leads)
simulation model Agl_HLMP7040 (Diode)
signal-integrity model LED
pins: 1 A, 2 K

## HLMP-P505-G0032
designator D?
Subminiature Green LED Lamp; LuminousIntensity: 1.6mcd (Minimum).; PCB_Layout: Complies with manufacturer's recommendation.; DrillSize: Nominal, Rounded to nearest 0.05mm
footprint 2.2X2.1X2.2Z (SM LED; 2 Z-Bend Leads)
simulation model Agl_HLMP7040 (Diode)
signal-integrity model LED
pins: 1 A, 2 K

## HLMP-P605-F0011
designator D?
Subminiature Green LED Lamp; LuminousIntensity: 1mcd (Minimum).; PCB_Layout: Complies with manufacturer's recommendation.
footprint 2.2X2.1X2.2 (SM LED; 2 Gull Wing Leads; Body 2.2 x 2.1 mm, (LxW))
simulation model Agl_HLMPQ605 (Diode)
signal-integrity model LED
pins: 1 A, 2 K

## HLMP-P605-F0021
designator D?
Subminiature Green LED Lamp; LuminousIntensity: 1mcd (Minimum).; PCB_Layout: Complies with manufacturer's recommendation.; DrillSize: Nominal, Rounded to nearest 0.05mm
footprint 2.2X2.1X2.2Y (SM LED; 2 Yoke Leads)
simulation model Agl_HLMPQ605 (Diode)
signal-integrity model LED
pins: 1 A, 2 K

## HLMP-P605-F0022
designator D?
Subminiature Green LED Lamp; LuminousIntensity: 1mcd (Minimum).; PCB_Layout: Complies with manufacturer's recommendation.; DrillSize: Nominal, Rounded to nearest 0.05mm
footprint 2.2X2.1X2.2Y (SM LED; 2 Yoke Leads)
simulation model Agl_HLMPQ605 (Diode)
signal-integrity model LED
pins: 1 A, 2 K

## HLMP-P605-F0031
designator D?
Subminiature Green LED Lamp; LuminousIntensity: 1mcd (Minimum).; PCB_Layout: Complies with manufacturer's recommendation.; DrillSize: Nominal, Rounded to nearest 0.05mm
footprint 2.2X2.1X2.2Z (SM LED; 2 Z-Bend Leads)
simulation model Agl_HLMPQ605 (Diode)
signal-integrity model LED
pins: 1 A, 2 K

## HLMP-Q100-M0012
designator D?
Subminiature Red LED Lamp; LuminousIntensity: 16mcd (Minimum).; PCB_Layout: Complies with manufacturer's recommendation.
footprint 2.2X2.1X2.9 (SM LED; 2 Gull Wing Leads; Body 2.2 x 2.1 mm, (LxW))
simulation model Agl_HLMPQ100 (Diode)
signal-integrity model LED
pins: 1 A, 2 K

## HLMP-Q100-N0011
designator D?
Subminiature Red LED Lamp; LuminousIntensity: 25mcd (Minimum).; PCB_Layout: Complies with manufacturer's recommendation.
footprint 2.2X2.1X2.9 (SM LED; 2 Gull Wing Leads; Body 2.2 x 2.1 mm, (LxW))
simulation model Agl_HLMPQ100 (Diode)
signal-integrity model LED
pins: 1 A, 2 K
